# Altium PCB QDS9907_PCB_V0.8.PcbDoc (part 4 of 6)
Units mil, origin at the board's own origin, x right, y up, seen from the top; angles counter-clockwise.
Board outline 3410.03 x 4010.03 mil, 8 copper layers (Top Layer, GND1, INT1, INT2, PWR1, GND2, GND3, Bottom Layer), stack 81.668 mil thick; 250 components, 129 nets, 7010 pads, 701 vias.
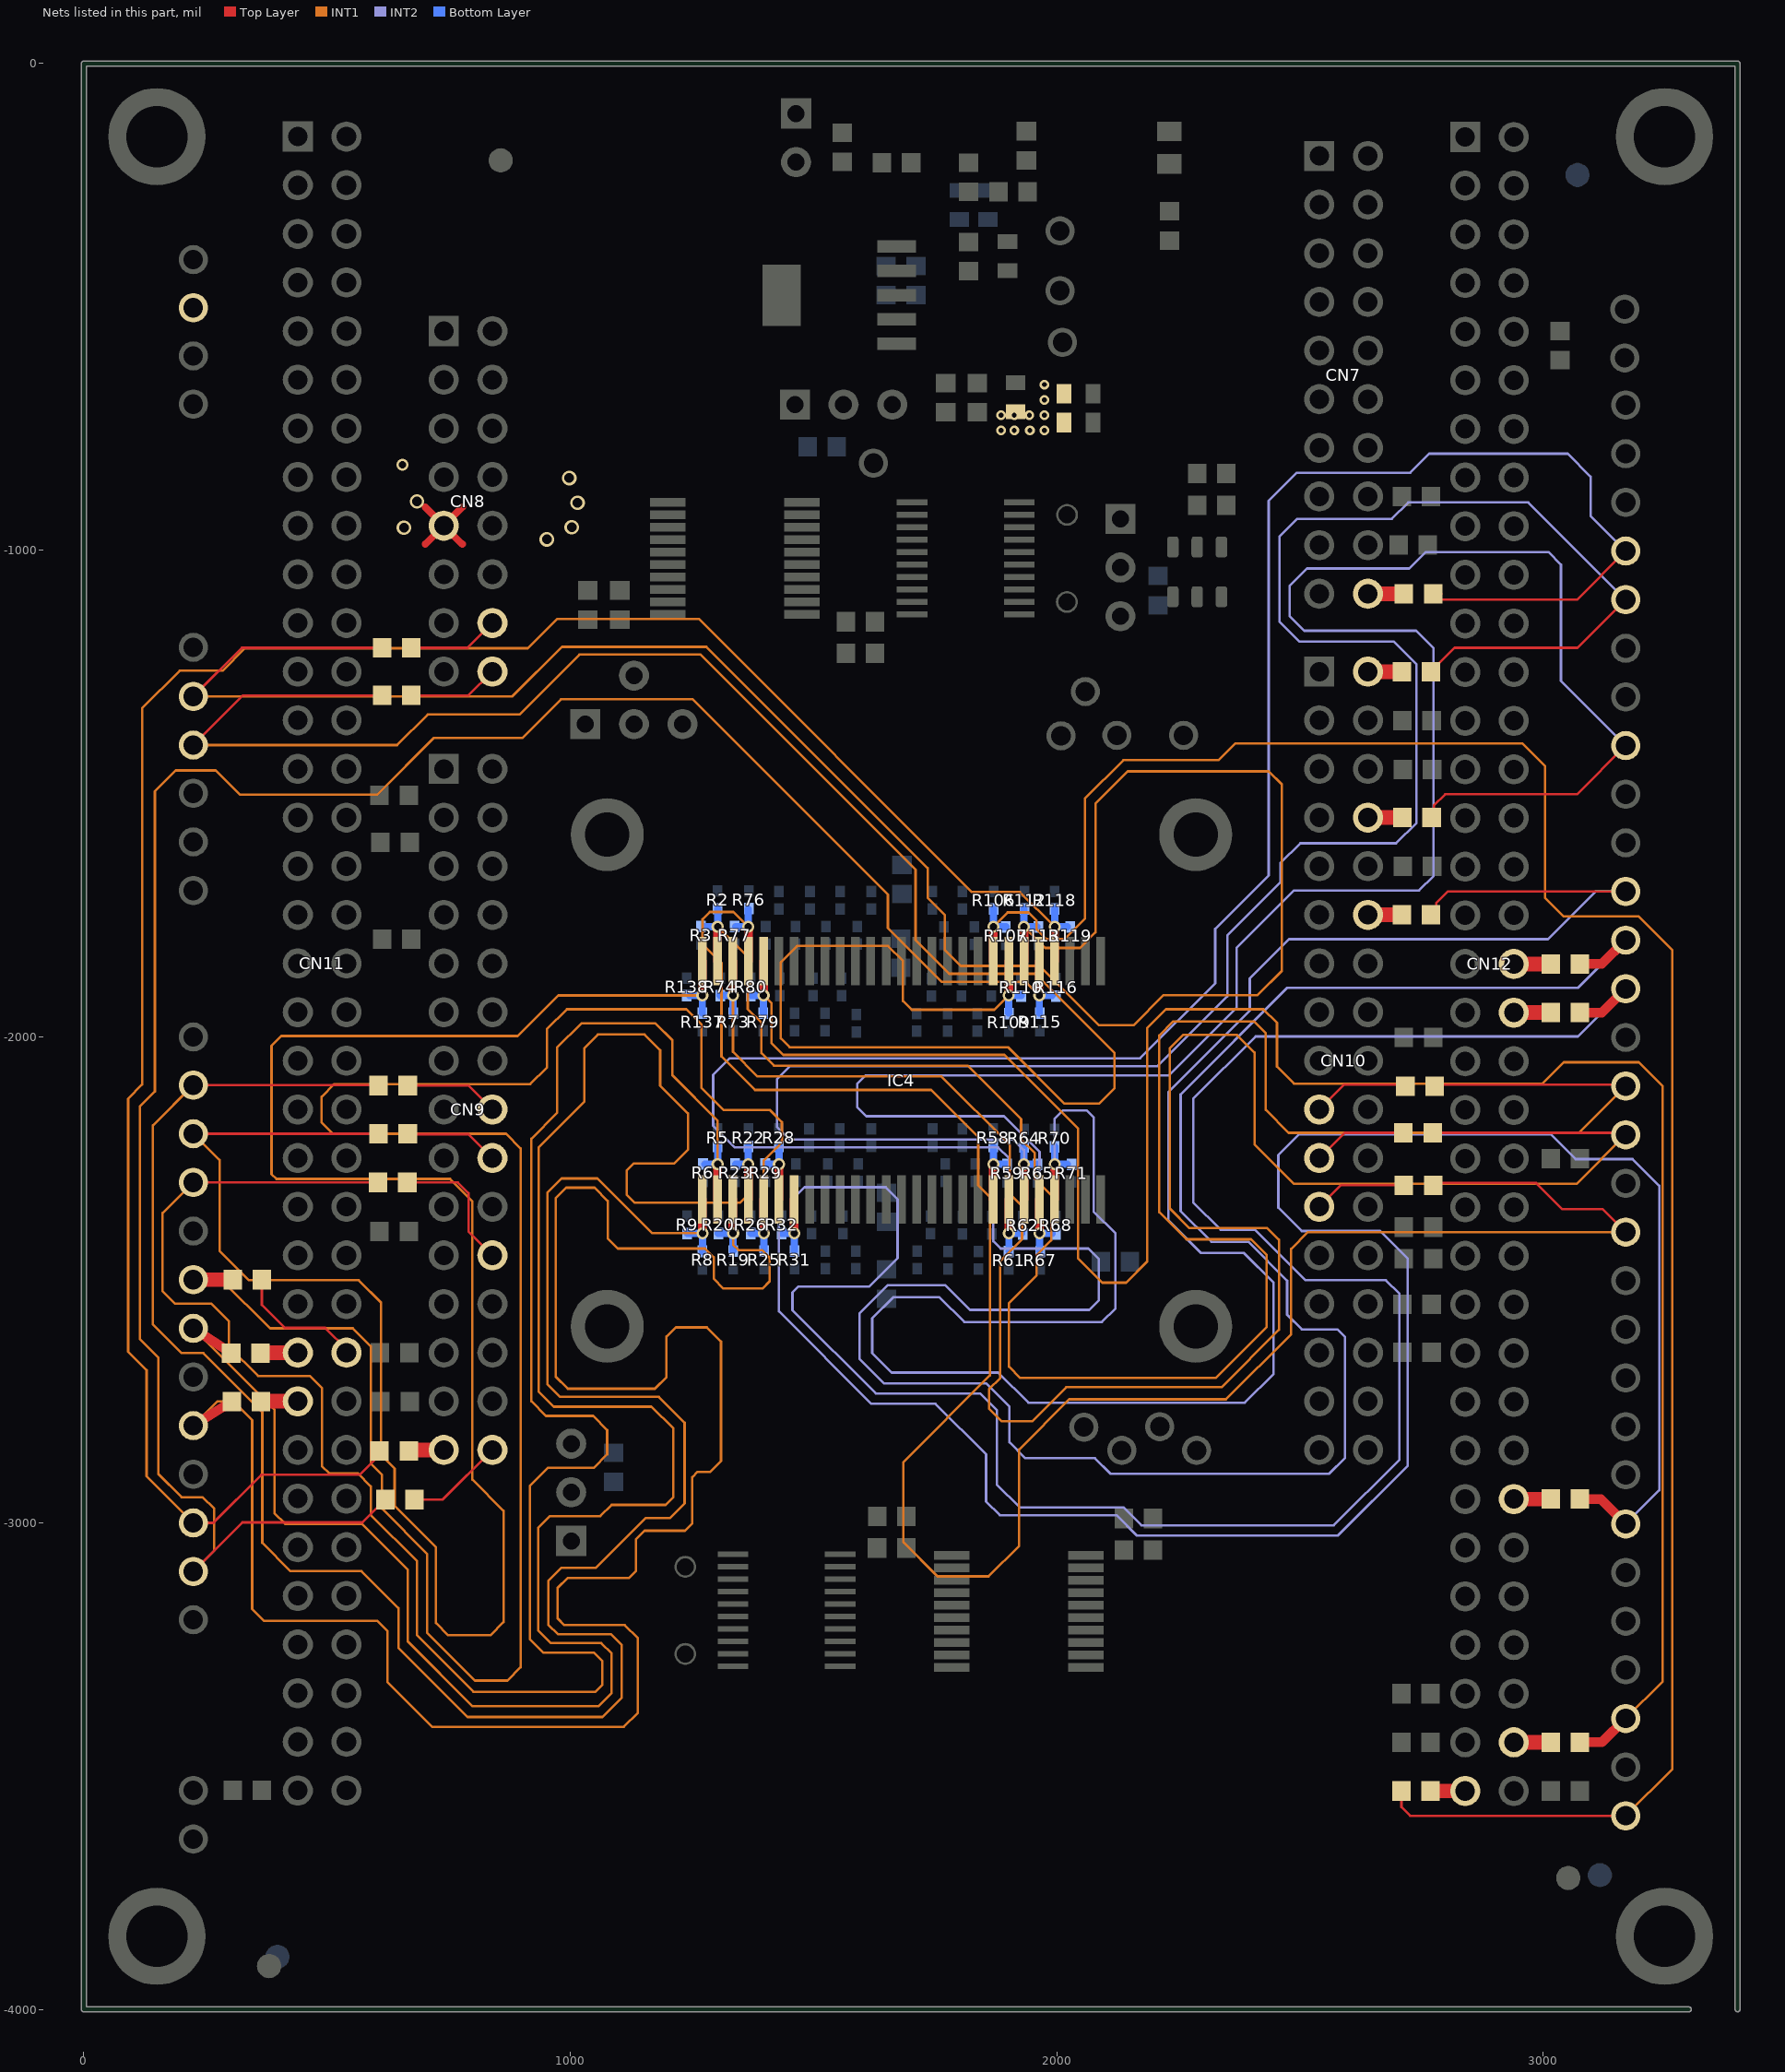
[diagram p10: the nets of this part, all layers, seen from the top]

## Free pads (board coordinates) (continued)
  round 1.28 on Bottom Overlay: ""(1652.55,-3885.99) ""(1652.55,-3885.99) ""(1652.55,-3885.73) ""(1652.55,-3884.7) ""(1652.55,-3884.39) ""(1652.55,-3884.39) ""(1652.55,-3885.99) ""(1652.55,-3885.99) ""(1652.55,-3885.73) ""(1652.55,-3884.7) ""(1652.55,-3884.39) ""(1652.55,-3884.39) ""(1652.97,-3883.68) ""(1652.97,-3883.68) ""(1652.99,-3886.76) ""(1652.99,-3886.76) ""(1653.57,-3882.65) ""(1653.57,-3882.65) ""(1653.58,-3887.79) ""(1653.58,-3887.79) ""(1653.64,-3887.9) ""(1653.64,-3887.9) ""(1653.64,-3887.9) ""(1653.64,-3887.9) ""(1654.17,-3881.62) ""(1654.17,-3881.62) ""(1654.34,-3888.82) ""(1654.34,-3888.82) ""(1654.78,-3880.59) ""(1654.78,-3880.59) ""(1655.13,-3889.84) ""(1655.13,-3889.84) ""(1655.38,-3879.57) ""(1655.38,-3879.57) ""(1655.91,-3890.87) ""(1655.91,-3890.87) ""(1655.98,-3878.54) ""(1655.98,-3878.54) ""(1656.14,-3816.83) ""(1656.14,-3816.83) ""(1656.14,-3816.83) ""(1656.14,-3816.83) ""(1656.15,-3816.88) ""(1656.15,-3816.88) ""(1656.23,-3815.85) ""(1656.23,-3815.85) ""(1656.26,-3817.91) ""(1656.26,-3817.91) ""(1656.33,-3814.82) ""(1656.33,-3814.82) ""(1656.37,-3818.94) ""(1656.37,-3818.94) ""(1656.43,-3813.8) ""(1656.43,-3813.8) ""(1656.48,-3819.96) ""(1656.48,-3819.96) ""(1656.52,-3812.77) ""(1656.52,-3812.77) ""(1656.58,-3877.51) ""(1656.58,-3877.51) ""(1656.59,-3820.99) ""(1656.59,-3820.99) ""(1656.62,-3811.74) ""(1656.62,-3811.74) ""(1656.7,-3822.02) ""(1656.7,-3891.9) ""(1656.7,-3891.9) ""(1656.71,-3810.71) ""(1656.71,-3810.71) ""(1656.81,-3809.69) ""(1656.81,-3809.69) ""(1656.81,-3823.05) ""(1656.81,-3823.05) ""(1656.9,-3808.66) ""(1656.91,-3808.66) ""(1656.92,-3824.07) ""(1656.92,-3824.07) ""(1657,-3807.63) ""(1657,-3807.63) ""(1657.03,-3825.1) ""(1657.03,-3825.1) ""(1657.1,-3806.6) ""(1657.1,-3806.6) ""(1657.1,-3825.75) ""(1657.1,-3825.75) ""(1657.1,-3825.75) ""(1657.1,-3825.75) ""(1657.19,-3876.48) ""(1657.19,-3876.48) ""(1657.19,-3805.58) ""(1657.19,-3805.58) ""(1657.2,-3826.13) ""(1657.2,-3826.13) ""(1657.29,-3876.32) ""(1657.29,-3876.32) ""(1657.29,-3876.32) ""(1657.29,-3876.32) ""(1657.29,-3804.55) ""(1657.29,-3804.55) ""(1657.38,-3876.48) ""(1657.38,-3876.48) ""(1657.38,-3803.52) ""(1657.38,-3803.52) ""(1657.43,-3803.03) ""(1657.43,-3803.03) ""(1657.43,-3803.03) ""(1657.43,-3803.03) ""(1657.45,-3827.16) ""(1657.45,-3827.16) ""(1657.49,-3892.93) ""(1657.49,-3892.93) ""(1657.57,-3802.49) ""(1657.57,-3802.49) ""(1657.71,-3828.18) ""(1657.71,-3828.18) ""(1657.72,-3893.23) ""(1657.72,-3893.23) ""(1657.72,-3893.23) ""(1657.72,-3893.23) ""(1657.83,-3801.47) ""(1657.83,-3801.47) ""(1657.95,-3877.51) ""(1657.95,-3877.51) ""(1657.97,-3829.21) ""(1658.09,-3800.44) ""(1658.09,-3800.44) ""(1658.22,-3830.24) ""(1658.22,-3830.24) ""(1658.36,-3799.41) ""(1658.36,-3799.41) ""(1658.42,-3878.35) ""(1658.42,-3878.35) ""(1658.42,-3878.35) ""(1658.42,-3878.35) ""(1658.48,-3831.27) ""(1658.48,-3831.27) ""(1658.62,-3798.38) ""(1658.62,-3798.38) ""(1658.64,-3878.54) ""(1658.64,-3878.54) ""(1658.72,-3893.95) ""(1658.73,-3893.95) ""(1658.74,-3832.29) ""(1658.74,-3832.29) ""(1658.88,-3797.35) ""(1658.89,-3797.35) ""(1659,-3833.32) ""(1659,-3833.32) ""(1659.15,-3796.33) ""(1659.15,-3796.33) ""(1659.25,-3834.35) ""(1659.25,-3834.35) ""(1659.41,-3795.3) ""(1659.41,-3795.3) ""(1659.51,-3835.38) ""(1659.51,-3835.38) ""(1659.67,-3836.02) ""(1659.67,-3836.02) ""(1659.67,-3836.02) ""(1659.67,-3836.02) ""(1659.68,-3794.27) ""(1659.68,-3794.27) ""(1659.82,-3836.41) ""(1659.82,-3836.41) ""(1659.88,-3879.57) ""(1659.88,-3879.57) ""(1659.94,-3793.24) ""(1659.94,-3793.24) ""(1660.15,-3894.98) ""(1660.15,-3894.98) ""(1660.2,-3792.22) ""(1660.2,-3792.22) ""(1660.21,-3837.43) ""(1660.21,-3837.43) ""(1660.47,-3791.19) ""(1660.47,-3791.19) ""(1660.61,-3838.46) ""(1660.61,-3838.46) ""(1660.65,-3790.48) ""(1660.65,-3790.48) ""(1660.65,-3790.48) ""(1660.65,-3790.48) ""(1660.65,-3880.22) ""(1660.65,-3880.22) ""(1660.66,-3880.22) ""(1660.66,-3880.22) ""(1660.77,-3790.16) ""(1660.77,-3790.16) ""(1661.01,-3839.49) ""(1661.01,-3839.49) ""(1661.17,-3789.13) ""(1661.17,-3789.13) ""(1661.34,-3880.59) ""(1661.34,-3880.59) ""(1661.4,-3840.52) ""(1661.4,-3840.52) ""(1661.57,-3788.11) ""(1661.57,-3788.11) ""(1661.57,-3896.01) ""(1661.57,-3896.01) ""(1661.8,-3841.54) ""(1661.8,-3841.54) ""(1661.97,-3787.08) ""(1661.97,-3787.08) ""(1662.19,-3842.57) ""(1662.19,-3842.57) ""(1662.37,-3786.05) ""(1662.37,-3786.05) ""(1662.59,-3843.6) ""(1662.59,-3843.6) ""(1662.76,-3785.02) ""(1662.76,-3785.02) ""(1662.89,-3844.39) ""(1662.89,-3844.39) ""(1662.89,-3844.39) ""(1662.89,-3844.39) ""(1663,-3897.04) ""(1663,-3897.04) ""(1663,-3844.63) ""(1663,-3844.63) ""(1663.16,-3783.99) ""(1663.16,-3783.99) ""(1663.19,-3881.62) ""(1663.19,-3881.62) ""(1663.36,-3897.3) ""(1663.36,-3897.3) ""(1663.36,-3897.3) ""(1663.36,-3897.3) ""(1663.48,-3845.65) ""(1663.48,-3845.65) ""(1663.56,-3782.97) ""(1663.56,-3782.97) ""(1663.95,-3846.68) ""(1663.95,-3846.68) ""(1663.96,-3781.94) ""(1663.96,-3781.94) ""(1663.99,-3882.07) ""(1663.99,-3882.07) ""(1663.99,-3882.07) ""(1663.99,-3882.07) ""(1664.36,-3780.91) ""(1664.36,-3780.91) ""(1664.42,-3847.71) ""(1664.42,-3847.71) ""(1664.48,-3780.6) ""(1664.48,-3780.6) ""(1664.48,-3780.6) ""(1664.48,-3780.6) ""(1664.89,-3898.06) ""(1664.89,-3898.06) ""(1664.9,-3848.74) ""(1664.9,-3848.74) ""(1665.01,-3779.88) ""(1665.01,-3779.88) ""(1665.37,-3849.76) ""(1665.37,-3849.76) ""(1665.77,-3778.86) ""(1665.77,-3778.86) ""(1665.85,-3850.79) ""(1665.85,-3850.79) ""(1666.32,-3851.82) ""(1666.32,-3851.82) ""(1666.53,-3777.83) ""(1666.53,-3777.83) ""(1666.73,-3852.7) ""(1666.73,-3852.7) ""(1666.73,-3852.7) ""(1666.73,-3852.7) ""(1666.85,-3852.85) ""(1666.85,-3852.85) ""(1666.95,-3899.09) ""(1666.95,-3899.09) ""(1667.29,-3776.8) ""(1667.29,-3776.8) ""(1667.32,-3882.07) ""(1667.32,-3882.07) ""(1667.32,-3882.07) ""(1667.32,-3882.07) ""(1667.67,-3853.88) ""(1667.67,-3853.88) ""(1668.05,-3775.77) ""(1668.05,-3775.77) ""(1668.5,-3854.9) ""(1668.5,-3854.9) ""(1668.82,-3774.75) ""(1668.82,-3774.75) ""(1669.01,-3900.12) ""(1669.01,-3900.12) ""(1669.32,-3855.93) ""(1669.32,-3855.93) ""(1669.58,-3773.72) ""(1669.58,-3773.72) ""(1670.14,-3856.96) ""(1670.14,-3856.96) ""(1670.31,-3900.77) ""(1670.31,-3900.77) ""(1670.31,-3900.77) ""(1670.31,-3900.77) ""(1670.34,-3772.69) ""(1670.34,-3772.69) ""(1670.85,-3772) ""(1670.85,-3772) ""(1670.85,-3772) ""(1670.85,-3772) ""(1670.96,-3857.99) ""(1670.96,-3857.99) ""(1671.16,-3881.72) ""(1671.16,-3881.72) ""(1671.16,-3881.72) ""(1671.16,-3881.72) ""(1671.19,-3771.66) ""(1671.19,-3771.66) ""(1671.39,-3881.62) ""(1671.39,-3881.62) ""(1671.79,-3859.01) ""(1671.79,-3859.01) ""(1671.91,-3901.15) ""(1671.91,-3901.15) ""(1672.22,-3770.64) ""(1672.22,-3770.64) ""(1672.61,-3860.04) ""(1672.61,-3860.04) ""(1673.06,-3860.61) ""(1673.06,-3860.61) ""(1673.07,-3860.61) ""(1673.07,-3860.61) ""(1673.25,-3769.61) ""(1673.25,-3769.61) ""(1673.66,-3861.07) ""(1673.66,-3861.07) ""(1673.86,-3880.59) ""(1673.86,-3880.59) ""(1674.28,-3768.58) ""(1674.28,-3768.58) ""(1675,-3862.1) ""(1675,-3862.1) ""(1675.31,-3767.55) ""(1675.31,-3767.55) ""(1675.35,-3879.97) ""(1675.35,-3879.97) ""(1675.35,-3879.97) ""(1675.35,-3879.97) ""(1675.63,-3902.02) ""(1675.63,-3902.02) ""(1675.63,-3902.02) ""(1675.63,-3902.02) ""(1676.03,-3879.57) ""(1676.03,-3879.57) ""(1676.33,-3766.52) ""(1676.33,-3766.52) ""(1676.34,-3863.12) ""(1676.34,-3863.12) ""(1677.36,-3765.5) ""(1677.36,-3765.5) ""(1677.4,-3902.18) ""(1677.4,-3902.18) ""(1677.67,-3864.15) ""(1677.67,-3864.15) ""(1677.75,-3878.54) ""(1677.75,-3878.54) ""(1677.86,-3765) ""(1677.86,-3765) ""(1677.86,-3765) ""(1677.86,-3765) ""(1678.52,-3878.07) ""(1678.52,-3878.07) ""(1678.52,-3878.07) ""(1678.52,-3878.07) ""(1678.73,-3764.47) ""(1678.73,-3764.47) ""(1679.01,-3865.18) ""(1679.01,-3865.18) ""(1680.35,-3866.21) ""(1680.35,-3866.21) ""(1680.42,-3763.44) ""(1680.42,-3763.44) ""(1680.96,-3877.51) ""(1680.96,-3877.51) ""(1681.33,-3866.97) ""(1681.33,-3866.97) ""(1681.33,-3866.97) ""(1681.33,-3866.97) ""(1681.87,-3867.23) ""(1681.87,-3867.23) ""(1682.11,-3762.41) ""(1682.11,-3762.41) ""(1682.52,-3877.15) ""(1682.52,-3877.15) ""(1682.52,-3877.15) ""(1682.52,-3877.15) ""(1682.87,-3902.65) ""(1682.87,-3902.65) ""(1682.87,-3902.65) ""(1682.87,-3902.65) ""(1683.8,-3761.39) ""(1683.8,-3761.39) ""(1683.93,-3868.26) ""(1683.93,-3868.26) ""(1685.17,-3760.55) ""(1685.17,-3760.55) ""(1685.17,-3760.55) ""(1685.17,-3760.55) ""(1685.34,-3902.18) ""(1685.34,-3902.18) ""(1685.6,-3760.36) ""(1685.6,-3760.36) ""(1685.99,-3869.29) ""(1685.99,-3869.29) ""(1687.2,-3876.48) ""(1687.2,-3876.48) ""(1687.82,-3759.33) ""(1687.82,-3759.33) ""(1688.05,-3870.32) ""(1688.05,-3870.32) ""(1689.31,-3876.18) ""(1689.31,-3876.18) ""(1689.31,-3876.18) ""(1689.31,-3876.18) ""(1689.57,-3871.08) ""(1689.57,-3871.08) ""(1689.57,-3871.08) ""(1689.57,-3871.08) ""(1690.05,-3758.3) ""(1690.05,-3758.3) ""(1690.69,-3901.15) ""(1690.69,-3901.15) ""(1690.8,-3871.35) ""(1690.8,-3871.35) ""(1691.09,-3901.07) ""(1691.09,-3901.07) ""(1691.09,-3901.07) ""(1691.09,-3901.07) ""(1692.28,-3757.28) ""(1692.28,-3757.28) ""(1693.46,-3756.73) ""(1693.46,-3756.73) ""(1693.46,-3756.73) ""(1693.46,-3756.73) ""(1693.83,-3900.12) ""(1693.83,-3900.12) ""(1694.88,-3875.46) ""(1694.88,-3875.46) ""(1695.53,-3872.37) ""(1695.53,-3872.37) ""(1695.8,-3756.25) ""(1695.8,-3756.25) ""(1696.65,-3823.05) ""(1696.65,-3823.05) ""(1696.65,-3822.02) ""(1696.65,-3822.02) ""(1696.65,-3820.99) ""(1696.65,-3820.99) ""(1696.65,-3819.96) ""(1696.65,-3819.96) ""(1696.65,-3818.94) ""(1696.65,-3818.94) ""(1696.65,-3817.91) ""(1696.65,-3817.91) ""(1696.65,-3816.88) ""(1696.65,-3816.88) ""(1696.65,-3815.85) ""(1696.65,-3815.85) ""(1696.65,-3814.82) ""(1696.65,-3814.82) ""(1696.65,-3813.8) ""(1696.65,-3813.8) ""(1696.65,-3812.77) ""(1696.65,-3812.77) ""(1696.65,-3811.74) ""(1696.65,-3811.74) ""(1696.65,-3810.71) ""(1696.65,-3810.71) ""(1696.65,-3809.69) ""(1696.65,-3809.69) ""(1696.65,-3808.66) ""(1696.65,-3808.66) ""(1696.65,-3807.63) ""(1696.65,-3807.63) ""(1696.65,-3806.6) ""(1696.65,-3806.6) ""(1696.69,-3824.07) ""(1696.69,-3824.07) ""(1696.71,-3805.58) ""(1696.71,-3805.58) ""(1696.74,-3825.1) ""(1696.74,-3825.1) ""(1696.76,-3804.55) ""(1696.76,-3804.55) ""(1696.78,-3899.09) ""(1696.78,-3899.09) ""(1696.8,-3826.13) ""(1696.8,-3826.13) ""(1696.82,-3803.52) ""(1696.82,-3803.52) ""(1696.86,-3827.16) ""(1696.86,-3827.16) ""(1696.87,-3802.49) ""(1696.87,-3802.49) ""(1696.92,-3828.18) ""(1696.92,-3828.18) ""(1696.93,-3801.47) ""(1696.93,-3801.47) ""(1696.97,-3829.21) ""(1696.98,-3800.44) ""(1696.98,-3800.44) ""(1697.03,-3830.24) ""(1697.03,-3830.24) ""(1697.03,-3799.41) ""(1697.03,-3799.41) ""(1697.09,-3831.27) ""(1697.09,-3798.38) ""(1697.09,-3831.27) ""(1697.09,-3798.38) ""(1697.14,-3797.35) ""(1697.14,-3797.35) ""(1697.15,-3832.29) ""(1697.15,-3832.29) ""(1697.2,-3796.33) ""(1697.2,-3796.33) ""(1697.2,-3833.32) ""(1697.2,-3833.32) ""(1697.25,-3795.3) ""(1697.25,-3795.3) ""(1697.26,-3834.35) ""(1697.26,-3834.35) ""(1697.3,-3794.27) ""(1697.3,-3794.27) ""(1697.32,-3835.38) ""(1697.32,-3835.38) ""(1697.36,-3793.24) ""(1697.36,-3793.24) ""(1697.37,-3836.41) ""(1697.37,-3836.41) ""(1697.41,-3792.22) ""(1697.41,-3792.22) ""(1697.43,-3837.43) ""(1697.43,-3837.43) ""(1697.47,-3791.19) ""(1697.47,-3791.19) ""(1697.49,-3838.46) ""(1697.49,-3838.46) ""(1697.52,-3790.16) ""(1697.52,-3790.16) ""(1697.55,-3839.49) ""(1697.55,-3839.49) ""(1697.58,-3789.13) ""(1697.58,-3789.13) ""(1697.6,-3840.52) ""(1697.6,-3840.52) ""(1697.63,-3788.11) ""(1697.63,-3788.11) ""(1697.75,-3841.54) ""(1697.75,-3841.54) ""(1697.9,-3787.08) ""(1697.9,-3787.08) ""(1697.97,-3842.57) ""(1697.97,-3842.57) ""(1698.16,-3786.05) ""(1698.16,-3786.05) ""(1698.19,-3843.6) ""(1698.19,-3843.6) ""(1698.34,-3898.55) ""(1698.34,-3898.55) ""(1698.34,-3898.55) ""(1698.34,-3898.55) ""(1698.41,-3844.63) ""(1698.41,-3844.63) ""(1698.43,-3785.02) ""(1698.43,-3785.02) ""(1698.63,-3845.65) ""(1698.63,-3845.65) ""(1698.69,-3783.99) ""(1698.69,-3783.99) ""(1698.85,-3846.68) ""(1698.85,-3846.68) ""(1698.95,-3782.97) ""(1698.95,-3782.97) ""(1699.04,-3898.06) ""(1699.04,-3898.06) ""(1699.07,-3847.71) ""(1699.07,-3847.71) ""(1699.22,-3781.94) ""(1699.22,-3781.94) ""(1699.29,-3848.74) ""(1699.29,-3848.74) ""(1699.48,-3780.91) ""(1699.48,-3780.91) ""(1699.51,-3849.76) ""(1699.51,-3849.76) ""(1699.74,-3779.88) ""(1699.74,-3779.88) ""(1699.8,-3850.79) ""(1699.8,-3850.79) ""(1700.01,-3778.86) ""(1700.01,-3778.86) ""(1700.13,-3851.82) ""(1700.13,-3851.82) ""(1700.26,-3873.4) ""(1700.26,-3873.4) ""(1700.27,-3777.83) ""(1700.27,-3777.83) ""(1700.45,-3852.85) ""(1700.45,-3852.85) ""(1700.51,-3897.04) ""(1700.51,-3897.04) ""(1700.54,-3776.8) ""(1700.54,-3776.8) ""(1700.77,-3755.22) ""(1700.77,-3755.22) ""(1700.78,-3853.88) ""(1700.78,-3853.88) ""(1700.8,-3775.77) ""(1700.8,-3775.77) ""(1701.1,-3854.9) ""(1701.1,-3854.9) ""(1701.31,-3774.75) ""(1701.31,-3774.75) ""(1701.43,-3855.93) ""(1701.43,-3855.93) ""(1701.95,-3773.72) ""(1701.95,-3773.72) ""(1701.98,-3856.96) ""(1701.98,-3856.96) ""(1701.98,-3896.01) ""(1701.98,-3896.01) ""(1702.59,-3772.69) ""(1702.59,-3772.69) ""(1702.66,-3857.99) ""(1702.66,-3857.99) ""(1702.7,-3754.82) ""(1702.7,-3754.82) ""(1702.7,-3754.82) ""(1702.7,-3754.82) ""(1702.77,-3874.43) ""(1702.77,-3874.43) ""(1703.23,-3771.66) ""(1703.23,-3771.66) ""(1703.35,-3859.01) ""(1703.35,-3859.01) ""(1703.45,-3894.98) ""(1703.45,-3894.98) ""(1703.88,-3770.64) ""(1703.88,-3770.64) ""(1704.16,-3874.25) ""(1704.16,-3874.25) ""(1704.16,-3874.25) ""(1704.16,-3874.25) ""(1704.4,-3860.04) ""(1704.4,-3860.04) ""(1704.92,-3893.95) ""(1704.92,-3893.95) ""(1705.24,-3769.61) ""(1705.24,-3769.61) ""(1705.55,-3861.07) ""(1705.55,-3861.07) ""(1706.38,-3892.93) ""(1706.38,-3892.93) ""(1707.17,-3768.58) ""(1707.17,-3768.58) ""(1707.39,-3862.1) ""(1707.39,-3862.1) ""(1707.85,-3891.9) ""(1707.85,-3891.9) ""(1707.91,-3891.86) ""(1707.91,-3891.86) ""(1707.91,-3891.86) ""(1707.91,-3891.86) ""(1708.94,-3890.87) ""(1708.94,-3890.87) ""(1710.02,-3889.84) ""(1710.02,-3889.84) ""(1711.09,-3888.82) ""(1711.09,-3888.82) ""(1711.83,-3754.19) ""(1711.83,-3754.19) ""(1712.02,-3754.18) ""(1712.02,-3754.18) ""(1712.02,-3754.18) ""(1712.02,-3754.18) ""(1712.16,-3887.79) ""(1712.16,-3887.79) ""(1712.37,-3754.19) ""(1712.37,-3754.19) ""(1713.24,-3886.76) ""(1713.24,-3886.76) ""(1713.51,-3863.12) ""(1713.51,-3863.12) ""(1714.07,-3863.12) ""(1714.07,-3863.12) ""(1714.31,-3885.73) ""(1714.31,-3885.73) ""(1715.38,-3884.7) ""(1715.38,-3884.7) ""(1715.66,-3884.44) ""(1715.66,-3884.44) ""(1715.66,-3884.44) ""(1715.66,-3884.44) ""(1716.29,-3768.58) ""(1716.29,-3768.58) ""(1716.38,-3883.68) ""(1716.39,-3883.68) ""(1716.89,-3862.1) ""(1716.89,-3862.1) ""(1717.36,-3882.65) ""(1717.36,-3882.65) ""(1718.25,-3769.61) ""(1718.25,-3769.61) ""(1718.34,-3861.07) ""(1718.34,-3861.07) ""(1718.34,-3881.62) ""(1718.34,-3881.62) ""(1719,-3770.64) ""(1719,-3770.64) ""(1719.32,-3880.59) ""(1719.32,-3880.59) ""(1719.37,-3860.04) ""(1719.37,-3860.04) ""(1719.75,-3771.66) ""(1719.75,-3771.66) ""(1720.29,-3879.57) ""(1720.29,-3879.57) ""(1720.4,-3859.01) ""(1720.4,-3859.01) ""(1720.5,-3772.69) ""(1720.5,-3772.69) ""(1720.62,-3754.5) ""(1720.62,-3754.5) ""(1720.62,-3754.5) ""(1720.62,-3754.5) ""(1720.85,-3857.99) ""(1720.85,-3857.99) ""(1721.07,-3773.72) ""(1721.07,-3773.72) ""(1721.25,-3856.96) ""(1721.27,-3878.54) ""(1721.27,-3878.54) ""(1721.51,-3774.75) ""(1721.51,-3774.75) ""(1721.66,-3855.93) ""(1721.66,-3855.93) ""(1721.93,-3877.84) ""(1721.93,-3877.84) ""(1721.93,-3877.84) ""(1721.93,-3877.84) ""(1721.95,-3775.77) ""(1721.95,-3775.77) ""(1722.06,-3854.9) ""(1722.06,-3854.9) ""(1722.39,-3776.8) ""(1722.39,-3776.8) ""(1722.41,-3877.51) ""(1722.41,-3877.51) ""(1722.46,-3853.88) ""(1722.46,-3853.88) ""(1722.81,-3777.83) ""(1722.81,-3777.83) ""(1722.87,-3852.85) ""(1722.87,-3852.85) ""(1723.12,-3778.86) ""(1723.12,-3778.86) ""(1723.27,-3851.82) ""(1723.27,-3851.82) ""(1723.3,-3755.22) ""(1723.3,-3755.22) ""(1723.43,-3779.88) ""(1723.43,-3779.88) ""(1723.53,-3850.79) ""(1723.53,-3850.79) ""(1723.71,-3849.76) ""(1723.71,-3849.76) ""(1723.74,-3780.91) ""(1723.74,-3780.91) ""(1723.89,-3848.74) ""(1723.89,-3848.74) ""(1723.9,-3876.48) ""(1723.9,-3876.48) ""(1723.91,-3781.94) ""(1723.91,-3781.94) ""(1724.06,-3847.71) ""(1724.06,-3847.71) ""(1724.08,-3782.97) ""(1724.08,-3782.97) ""(1724.24,-3846.68) ""(1724.24,-3846.68) ""(1724.24,-3783.99) ""(1724.24,-3783.99) ""(1724.41,-3785.02) ""(1724.41,-3785.02) ""(1724.42,-3845.65) ""(1724.42,-3845.65) ""(1724.57,-3786.05) ""(1724.57,-3786.05) ""(1724.6,-3844.63) ""(1724.6,-3844.63) ""(1724.74,-3787.08) ""(1724.74,-3787.08) ""(1724.77,-3843.6) ""(1724.77,-3843.6) ""(1724.91,-3788.11) ""(1724.91,-3788.11) ""(1724.95,-3842.57) ""(1724.95,-3842.57) ""(1725.07,-3789.13) ""(1725.07,-3789.13) ""(1725.1,-3841.54) ""(1725.1,-3841.54) ""(1725.21,-3840.52) ""(1725.21,-3840.52) ""(1725.24,-3790.16) ""(1725.24,-3790.16) ""(1725.33,-3839.49) ""(1725.33,-3839.49) ""(1725.38,-3875.46) ""(1725.38,-3875.46) ""(1725.4,-3791.19) ""(1725.4,-3791.19) ""(1725.44,-3838.46) ""(1725.44,-3838.46) ""(1725.49,-3792.22) ""(1725.49,-3792.22) ""(1725.55,-3837.43) ""(1725.55,-3837.43) ""(1725.59,-3793.24) ""(1725.59,-3793.24) ""(1725.66,-3836.41) ""(1725.66,-3836.41) ""(1725.68,-3794.27) ""(1725.68,-3794.27) ""(1725.77,-3835.38) ""(1725.77,-3835.38) ""(1725.78,-3795.3) ""(1725.78,-3795.3) ""(1725.88,-3796.33) ""(1725.88,-3796.33) ""(1725.88,-3834.35) ""(1725.88,-3834.35) ""(1725.97,-3797.35) ""(1725.97,-3797.35) ""(1726,-3833.32) ""(1726,-3833.32) ""(1726.07,-3798.38) ""(1726.07,-3798.38) ""(1726.11,-3832.29) ""(1726.11,-3832.29) ""(1726.17,-3799.41) ""(1726.17,-3799.41) ""(1726.22,-3831.27) ""(1726.22,-3831.27) ""(1726.26,-3800.44) ""(1726.26,-3800.44) ""(1726.33,-3830.24) ""(1726.33,-3830.24) ""(1726.36,-3801.47) ""(1726.36,-3801.47) ""(1726.41,-3802.49) ""(1726.41,-3802.49) ""(1726.44,-3829.21) ""(1726.44,-3829.21) ""(1726.46,-3803.52) ""(1726.46,-3803.52) ""(1726.52,-3804.55) ""(1726.52,-3804.55) ""(1726.55,-3828.18) ""(1726.55,-3828.18) ""(1726.57,-3805.58) ""(1726.57,-3805.58) ""(1726.62,-3806.6) ""(1726.62,-3806.6) ""(1726.67,-3827.16) ""(1726.67,-3827.16) ""(1726.67,-3807.63) ""(1726.67,-3807.63) ""(1726.71,-3826.13) ""(1726.71,-3826.13) ""(1726.72,-3808.66) ""(1726.72,-3808.66) ""(1726.74,-3825.1) ""(1726.74,-3825.1) ""(1726.76,-3824.07) ""(1726.76,-3824.07) ""(1726.77,-3809.69) ""(1726.77,-3809.69) ""(1726.79,-3823.05) ""(1726.79,-3823.05) ""(1726.82,-3822.02) ""(1726.82,-3822.02) ""(1726.82,-3810.71) ""(1726.82,-3810.71) ""(1726.85,-3820.99) ""(1726.85,-3820.99) ""(1726.87,-3874.43) ""(1726.87,-3874.43) ""(1726.87,-3819.96) ""(1726.87,-3819.96) ""(1726.88,-3811.74) ""(1726.88,-3811.74) ""(1726.9,-3818.94) ""(1726.9,-3818.94) ""(1726.93,-3812.77) ""(1726.93,-3812.77) ""(1726.93,-3817.91) ""(1726.93,-3817.91) ""(1726.95,-3816.88) ""(1726.95,-3816.88) ""(1726.98,-3813.8) ""(1726.98,-3813.8) ""(1726.98,-3815.85) ""(1726.98,-3815.85) ""(1727.01,-3814.82) ""(1727.01,-3814.82) ""(1727.12,-3756.25) ""(1727.12,-3756.25) ""(1728.35,-3873.4) ""(1728.35,-3873.4) ""(1728.9,-3756.72) ""(1728.9,-3756.72) ""(1728.9,-3756.72) ""(1728.9,-3756.72) ""(1729.84,-3872.37) ""(1729.84,-3872.37) ""(1730.27,-3757.28) ""(1730.27,-3757.28) ""(1730.61,-3871.84) ""(1730.61,-3871.84) ""(1730.61,-3871.84) ""(1730.61,-3871.84) ""(1731.6,-3871.35) ""(1731.6,-3871.35) ""(1732.85,-3758.3) ""(1732.85,-3758.3) ""(1733.66,-3870.32) ""(1733.66,-3870.32) ""(1735.31,-3759.29) ""(1735.31,-3759.29) ""(1735.31,-3759.29) ""(1735.31,-3759.29) ""(1735.4,-3759.33) ""(1735.4,-3759.33) ""(1735.72,-3869.29) ""(1735.72,-3869.29) ""(1737.45,-3760.36) ""(1737.45,-3760.36) ""(1737.77,-3868.26) ""(1737.77,-3868.26) ""(1738.49,-3867.91) ""(1738.49,-3867.91) ""(1738.49,-3867.91) ""(1738.49,-3867.91) ""(1739.51,-3761.39) ""(1739.51,-3761.39) ""(1739.64,-3867.23) ""(1739.64,-3867.23) ""(1741.05,-3762.15) ""(1741.05,-3762.15) ""(1741.05,-3762.15) ""(1741.05,-3762.15) ""(1741.4,-3866.21) ""(1741.4,-3866.21) ""(1741.41,-3762.41) ""(1741.41,-3762.41) ""(1742.85,-3763.44) ""(1742.85,-3763.44) ""(1743.17,-3865.18) ""(1743.17,-3865.18) ""(1744.29,-3764.47) ""(1744.29,-3764.47) ""(1744.93,-3864.15) ""(1744.93,-3864.15) ""(1745.73,-3765.5) ""(1745.73,-3765.5) ""(1746.19,-3863.41) ""(1746.19,-3863.41) ""(1746.19,-3863.41) ""(1746.19,-3863.41) ""(1746.54,-3863.12) ""(1746.54,-3863.12) ""(1747.17,-3766.52) ""(1747.17,-3766.52) ""(1747.73,-3766.93) ""(1747.73,-3766.93) ""(1747.73,-3766.93) ""(1747.73,-3766.93) ""(1747.78,-3862.1) ""(1747.78,-3862.1) ""(1748.36,-3767.55) ""(1748.36,-3767.55) ""(1749.01,-3861.07) ""(1749.01,-3861.07) ""(1749.39,-3768.58) ""(1749.39,-3768.58) ""(1750.25,-3860.04) ""(1750.25,-3860.04) ""(1750.42,-3769.61) ""(1750.42,-3769.61) ""(1751.45,-3770.64) ""(1751.45,-3770.64) ""(1751.48,-3859.01) ""(1751.48,-3859.01) ""(1751.86,-3858.7) ""(1751.86,-3858.7) ""(1751.86,-3858.7) ""(1751.86,-3858.7) ""(1752.35,-3857.99) ""(1752.35,-3857.99) ""(1752.47,-3771.66) ""(1752.47,-3771.66) ""(1753.07,-3856.96) ""(1753.07,-3856.96) ""(1753.5,-3772.69) ""(1753.5,-3772.69) ""(1753.78,-3855.93) ""(1753.79,-3855.93) ""(1753.8,-3772.99) ""(1753.8,-3772.99) ""(1753.8,-3772.99) ""(1753.8,-3772.99) ""(1754.36,-3773.72) ""(1754.36,-3773.72) ""(1754.5,-3854.9) ""(1754.5,-3854.9) ""(1755.15,-3774.75) ""(1755.15,-3774.75) ""(1755.22,-3853.88) ""(1755.22,-3853.88) ""(1755.93,-3852.85) ""(1755.93,-3852.85) ""(1755.93,-3775.77) ""(1755.93,-3775.77) ""(1756.65,-3851.82) ""(1756.65,-3851.82) ""(1756.72,-3776.8) ""(1756.72,-3776.8) ""(1756.96,-3851.37) ""(1756.96,-3851.37) ""(1756.96,-3851.37) ""(1756.96,-3851.37) ""(1757.31,-3850.79) ""(1757.31,-3850.79) ""(1757.51,-3777.83) ""(1757.51,-3777.83) ""(1757.92,-3778.37) ""(1757.92,-3778.37) ""(1757.92,-3778.37) ""(1757.92,-3778.37) ""(1757.92,-3849.76) ""(1757.92,-3849.76) ""(1758.16,-3778.86) ""(1758.16,-3778.86) ""(1758.54,-3848.74) ""(1758.54,-3848.74) ""(1758.68,-3779.88) ""(1758.68,-3779.88) ""(1759.16,-3847.71) ""(1759.16,-3847.71) ""(1759.19,-3780.91) ""(1759.19,-3780.91) ""(1759.71,-3781.94) ""(1759.71,-3781.94) ""(1759.77,-3846.68) ""(1759.78,-3846.68) ""(1759.81,-3846.62) ""(1759.81,-3846.62) ""(1759.81,-3846.62) ""(1759.81,-3846.62) ""(1760.18,-3845.65) ""(1760.18,-3845.65) ""(1760.22,-3782.97) ""(1760.22,-3782.97) ""(1760.57,-3844.63) ""(1760.57,-3844.63) ""(1760.74,-3783.99) ""(1760.74,-3783.99) ""(1760.96,-3843.6) ""(1760.96,-3843.6) ""(1761.25,-3785.02) ""(1761.25,-3785.02) ""(1761.35,-3842.57) ""(1761.35,-3842.57) ""(1761.41,-3785.34) ""(1761.41,-3785.34) ""(1761.41,-3785.34) ""(1761.41,-3785.34) ""(1761.62,-3786.05) ""(1761.62,-3786.05) ""(1761.74,-3841.54) ""(1761.74,-3841.54) ""(1761.93,-3787.08) ""(1761.93,-3787.08) ""(1762.13,-3840.52) ""(1762.13,-3840.52) ""(1762.24,-3788.11) ""(1762.24,-3788.11) ""(1762.52,-3839.49) ""(1762.52,-3839.49) ""(1762.55,-3789.13) ""(1762.55,-3789.13) ""(1762.86,-3790.16) ""(1762.86,-3790.16) ""(1762.91,-3838.46) ""(1762.91,-3838.46) ""(1763.16,-3791.19) ""(1763.16,-3791.19) ""(1763.3,-3837.43) ""(1763.3,-3837.43) ""(1763.33,-3837.36) ""(1763.33,-3837.36) ""(1763.33,-3837.36) ""(1763.33,-3837.36) ""(1763.47,-3792.22) ""(1763.47,-3792.22) ""(1763.52,-3836.41) ""(1763.52,-3836.41) ""(1763.72,-3835.38) ""(1763.73,-3835.38) ""(1763.78,-3793.24) ""(1763.78,-3793.24) ""(1763.93,-3834.35) ""(1763.93,-3834.35) ""(1764.09,-3794.27) ""(1764.09,-3794.27) ""(1764.14,-3833.32) ""(1764.14,-3833.32) ""(1764.31,-3794.99) ""(1764.31,-3794.99) ""(1764.31,-3794.99) ""(1764.31,-3794.99) ""(1764.34,-3832.29) ""(1764.34,-3832.29) ""(1764.38,-3795.3) ""(1764.38,-3795.3) ""(1764.55,-3831.27) ""(1764.55,-3831.27) ""(1764.64,-3796.33) ""(1764.64,-3796.33) ""(1764.75,-3830.24) ""(1764.75,-3830.24) ""(1764.9,-3797.35) ""(1764.9,-3797.35) ""(1764.93,-3829.34) ""(1764.93,-3829.34) ""(1764.93,-3829.34) ""(1764.93,-3829.34) ""(1764.95,-3829.21) ""(1764.95,-3829.21) ""(1765.11,-3828.18) ""(1765.11,-3828.18) ""(1765.15,-3798.38) ""(1765.16,-3798.38) ""(1765.26,-3827.16) ""(1765.26,-3827.16) ""(1765.41,-3826.13) ""(1765.41,-3826.13) ""(1765.41,-3799.41) ""(1765.41,-3799.41) ""(1765.56,-3825.1) ""(1765.56,-3825.1) ""(1765.58,-3800.1) ""(1765.58,-3800.1) ""(1765.58,-3800.1) ""(1765.58,-3800.1) ""(1765.62,-3800.44) ""(1765.62,-3800.44) ""(1765.71,-3824.07) ""(1765.71,-3824.07) ""(1765.73,-3801.47) ""(1765.73,-3801.47) ""(1765.83,-3802.49) ""(1765.83,-3802.49) ""(1765.87,-3823.05) ""(1765.87,-3823.05) ""(1765.94,-3803.52) ""(1765.94,-3803.52) ""(1766.02,-3822.02) ""(1766.02,-3822.02) ""(1766.04,-3804.55) ""(1766.04,-3804.55) ""(1766.15,-3805.58) ""(1766.15,-3805.58) ""(1766.17,-3820.99) ""(1766.17,-3820.99) ""(1766.22,-3820.64) ""(1766.22,-3820.64) ""(1766.22,-3820.64) ""(1766.22,-3820.64) ""(1766.24,-3819.96) ""(1766.24,-3819.96) ""(1766.26,-3806.6) ""(1766.26,-3806.6) ""(1766.27,-3818.94) ""(1766.27,-3818.94) ""(1766.3,-3817.91) ""(1766.3,-3817.91) ""(1766.33,-3816.88) ""(1766.33,-3816.88) ""(1766.36,-3815.85) ""(1766.36,-3815.85) ""(1766.36,-3807.63) ""(1766.36,-3807.63) ""(1766.39,-3814.82) ""(1766.39,-3814.82) ""(1766.42,-3813.8) ""(1766.42,-3813.8) ""(1766.45,-3812.77) ""(1766.45,-3812.77) ""(1766.47,-3808.66) ""(1766.47,-3808.66) ""(1766.48,-3811.74) ""(1766.48,-3811.74) ""(1766.51,-3810.71) ""(1766.51,-3810.71) ""(1766.54,-3809.69) ""(1766.54,-3809.69) ""(1766.54,-3809.38) ""(1766.54,-3809.38) ""(1766.55,-3809.38) ""(1766.55,-3809.38)
  round 1.29 on Bottom Overlay: ""(1656.7,-3822.02) ""(1657.97,-3829.21) ""(1696.97,-3829.21) ""(1721.26,-3856.96)
  round 1.8 on Bottom Overlay: ""(1696.65,-3823.36) ""(1696.65,-3823.36) ""(1696.65,-3806.72) ""(1696.65,-3806.72) ""(1697.63,-3840.98) ""(1697.63,-3840.98) ""(1697.63,-3788.13) ""(1697.63,-3788.13) ""(1697.63,-3840.98) ""(1697.63,-3840.98) ""(1697.63,-3788.13) ""(1697.63,-3788.13) ""(1699.59,-3850.11) ""(1699.59,-3850.11) ""(1699.59,-3850.11) ""(1699.59,-3850.11) ""(1700.89,-3775.4) ""(1700.89,-3775.4) ""(1700.89,-3775.4) ""(1700.89,-3775.4) ""(1701.55,-3856.31) ""(1701.55,-3856.31) ""(1701.55,-3856.31) ""(1701.55,-3856.31) ""(1703.51,-3859.25) ""(1703.51,-3859.25) ""(1704.16,-3770.18) ""(1704.16,-3770.18) ""(1704.16,-3770.18) ""(1704.16,-3770.18) ""(1709.06,-3767.58) ""(1709.06,-3767.58) ""(1709.06,-3767.58) ""(1709.06,-3767.58) ""(1710.36,-3862.84) ""(1710.36,-3862.84) ""(1710.36,-3862.84) ""(1710.36,-3862.84) ""(1713.95,-3863.16) ""(1713.95,-3863.16) ""(1713.95,-3863.16) ""(1713.95,-3863.16) ""(1714.28,-3767.58) ""(1714.28,-3767.58) ""(1714.28,-3767.58) ""(1714.28,-3767.58) ""(1717.55,-3861.86) ""(1717.55,-3861.86) ""(1718.2,-3769.53) ""(1718.2,-3769.53) ""(1718.2,-3769.53) ""(1718.2,-3769.53) ""(1720.81,-3773.12) ""(1720.81,-3773.12) ""(1722.77,-3777.69) ""(1722.77,-3777.69) ""(1722.77,-3777.69) ""(1722.77,-3777.69) ""(1723.42,-3851.42) ""(1723.42,-3851.42) ""(1723.42,-3851.42) ""(1723.42,-3851.42) ""(1726.69,-3826.95) ""(1726.69,-3826.95) ""(1727.02,-3814.55) ""(1727.02,-3814.55) ""(1727.02,-3814.55) ""(1727.02,-3814.55)

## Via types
v1: diameter 25, hole 15, Top Layer to Bottom Layer, tented both sides, 623 vias
v2: diameter 20, hole 10, Top Layer to Bottom Layer, tented both sides, 59 vias
v3: diameter 30, hole 20, Top Layer to Bottom Layer, tented both sides, 19 vias

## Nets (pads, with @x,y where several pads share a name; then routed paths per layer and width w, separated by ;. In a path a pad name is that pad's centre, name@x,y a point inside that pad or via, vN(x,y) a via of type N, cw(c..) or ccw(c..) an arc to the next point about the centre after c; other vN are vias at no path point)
+5V0: +5V0.1 C19.1 C20.1 CN8.9 L1.1 | length 215
  Top Layer w15: 702,-988 CN8.9@740,-950 ; 702,-912 CN8.9@740,-950 ; 778,-988 CN8.9@740,-950 ; 778,-912 CN8.9@740,-950
  other v1: 655,-825
  other v2: 1886,-754 1913,-754 1945,-754 1975,-754 1886,-722.67 1913,-722.67 1944,-722.67 1975,-722.67 1975,-691.33 1975,-660
  other v3: 952,-978 658,-954 1003,-953 1015,-903 685,-900 998,-852
A0: A0.1 IC4.3 R18.2 R19.2 R20.2 | length 4527.1
  Top Layer w5: R18.2@304,-2756 R18.2@304,-2751
  Top Layer w18: v1@1334.54,-2404.54 IC4.3@1334.54,-2335
  Top Layer w20: A0.1@225,-2800 R18.2@304,-2751
  INT1 w5: A0.1@225,-2800 275,-2750 307,-2750 346,-2789 346,-3177 370,-3201 603,-3201 624,-3222 624,-3327 716,-3419 1110,-3419 1139,-3390 1139,-3237 1112,-3210 988,-3210 974,-3196 974,-3134 995,-3113 1121,-3113 1135,-3099 1135,-3034 1153,-3016 1236,-3016 1251,-3001 1251,-2906 1262,-2895 1288,-2895 1310,-2873 1310,-2627 1281,-2598 1217,-2598 1198,-2617 1198,-2700 1174,-2724 995,-2724 970,-2699 970,-2333 992,-2311 1050,-2311 1077,-2338 1077,-2415 1098,-2436 1277,-2436 1295,-2454 1295,-2498 1315,-2518 1395,-2518 1410,-2503 1410,-2455 1394,-2439 1346,-2439 1334.99,-2427.99 v1(1334.99,-2404.54)
  Bottom Layer w5: v1@1334.54,-2405 v1(1334.99,-2404.54) ; R19.2@1334.99,-2440.54 R19.2@1335.45,-2441
  Bottom Layer w15: R20.2@1304.45,-2405 v1@1334.54,-2405 ; R19.2@1334.99,-2440.54 v1(1334.99,-2404.54)
A0_1: CN11.53 R18.1 | length 68
  Top Layer w30: R18.1@373,-2750 CN11.53@440,-2750 CN11.53@441,-2750
A1: A1.1 IC4.4 R21.1 R22.2 R23.2 | length 4527.9
  Top Layer w5: R21.1@303,-2651 R21.1@303,-2646
  Top Layer w18: IC4.4@1366.04,-2335 v1(1366.04,-2262.46)
  Top Layer w20: A1.1@225,-2600 R21.1@303,-2651
  INT1 w5: A1.1@225,-2600 392,-2767 392,-2980 414,-3002 571.5,-3002 666,-3096.5 666,-3244 799,-3377 1058,-3377 1085,-3350 1085,-3268 1064,-3247 960,-3247 934,-3221 934,-3010 958,-2986 1062,-2986 1085,-2963 1196,-2963 1212,-2947 1212,-2806 1167,-2761 966,-2761 935,-2730 935,-2228 1029,-2134 1029,-2024 1057,-1996 1153,-1996 1185,-2028 1185,-2101 1242,-2158 1242,-2233 1214,-2261 1131,-2261 1116,-2276 1116,-2325 1133,-2342 1349,-2342 1366.04,-2324.96 v1(1366.04,-2262.46)
  Bottom Layer w15: R23.2@1339.96,-2262.46 v1(1366.04,-2262.46) R22.2@1366.04,-2226.46
A1_1: CN11.51 R21.2 | length 68
  Top Layer w30: R21.2@372,-2650 CN11.51@440,-2650
A2: A2.1 IC4.5 R24.1 R25.2 R26.2 | length 4549.7
  Top Layer w18: v1@1397.54,-2404.54 IC4.5@1397.54,-2335
  Top Layer w30: A2.1@225,-2500 R24.1@306,-2500
  INT1 w5: A2.1@225,-2500 283,-2500 383,-2600 553,-2600 590,-2637 590,-2878 613,-2901 613,-2971 706,-3064 706,-3226 804,-3324 871,-3324 898,-3297 898,-2230 868,-2200 512,-2200 489,-2177 489,-2124 515,-2098 918,-2098 952,-2064 952,-1985 993,-1944 1239,-1944 1270,-1975 1270,-2106 1315,-2151 1410,-2151 1435,-2176 1435,-2218 1397.98,-2255.02 v1(1397.98,-2404.54)
  Bottom Layer w15: R26.2@1371.91,-2404.54 v1(1397.98,-2404.54) R25.2@1397.98,-2440.54
A2_1: CN11.52 R24.2 | length 277.8
  Top Layer w5: R24.2@366,-2500 366,-2552 413,-2599 496.24,-2599 CN11.52@542.12,-2644.88
  Top Layer w20: CN11.52@540,-2650 cw(c547.24,-2650) 542.11,-2644.89 CN11.52@540,-2650
A3: A3.1 IC4.6 R27.1 R28.2 R29.2 | length 4563.5
  Top Layer w18: IC4.6@1429.03,-2335 v1(1429.03,-2262.46)
  Top Layer w20: R27.1@3076,-2951 3119,-2951 A3.1@3170,-3002
  INT2 w5: v1(1429.03,-2262.46) 1429.03,-2565.03 1619,-2755 1751,-2755 1855,-2859 1855,-2956 1883,-2984 2123,-2984 2165,-3026 2578,-3026 2722,-2882 2722,-2457 2665,-2400 2504,-2400 2456,-2352 2456,-2244 2499,-2201 3016,-2201 3067,-2252 3184,-2252 3239,-2307 3239,-2933 A3.1@3170,-3002
  Bottom Layer w15: R29.2@1402.95,-2262.46 v1(1429.03,-2262.46) R28.2@1429.03,-2226.46
A3_1: CN12.58 R27.2 | length 76
  Top Layer w30: CN12.58@2940,-2951 R27.2@3016,-2951
A4: A4.1 IC4.7 R30.1 R31.2 R32.2 | length 4569
  Top Layer w18: v1@1460.53,-2404.54 IC4.7@1460.53,-2335
  Top Layer w20: R30.1@3076,-1951 3121,-1951 A4.1@3170,-1902
  INT2 w5: v1(1460.98,-2404.54) 1460.98,-2331.02 1482,-2310 1648.55,-2310 1673,-2334.45 1673,-2456 1615,-2514 1469,-2514 1457,-2526 1457,-2563 1628,-2734 1843,-2734 1877,-2768 1877,-2921 1924,-2968 2137,-2968 2174,-3005 2570,-3005 2705,-2870 2705,-2529 2677,-2501 2512,-2501 2408,-2397 2337,-2397 2281,-2341 2281,-2128 2409,-2000 3072,-2000 A4.1@3170,-1902
  Bottom Layer w15: R32.2@1434.9,-2404.54 v1(1460.98,-2404.54) R31.2@1460.98,-2440.54
A4_1: CN12.38 R30.2 | length 76
  Top Layer w30: CN12.38@2940,-1951 R30.2@3016,-1951
A5: A5.1 IC4.20 R57.1 R58.2 R59.2 | length 4536
  Top Layer w18: IC4.20@1869.98,-2335 v1(1869.98,-2262.46)
  Top Layer w20: R57.1@3076,-1851 3121,-1851 A5.1@3170,-1802
  INT2 w5: v1(1869.98,-2262.46) 1869.98,-2421 1884.98,-2436 2065,-2436 2087,-2458 2087,-2542 2067,-2562 1822,-2562 1771,-2511 1653,-2511 1595,-2569 1595,-2663 1645,-2713 1855,-2713 1903,-2761 1903,-2834 1936,-2867 2078.76,-2867 2110.76,-2899 2560,-2899 2593,-2866 2593,-2618 2577,-2602 2504,-2602 2474,-2572 2474,-2502 2394,-2422 2318,-2422 2255,-2359 2255,-2119 2474,-1900 3072,-1900 A5.1@3170,-1802
  Bottom Layer w15: R58.2@1869.98,-2226.46 v1(1869.98,-2262.46) R59.2@1896.05,-2262.46
A5_1: CN12.36 R57.2 | length 76
  Top Layer w30: CN12.36@2940,-1851 R57.2@3016,-1851
A6: A6.1 IC4.21 R60.1 R61.2 R62.2 | length 4540.5
  Top Layer w5: R60.1@2763,-1090 R60.1@2791,-1090 ; R60.1@2777,-1102 3070,-1102 A6.1@3170,-1002
  Top Layer w18: v1@1901.47,-2404.54 IC4.21@1901.47,-2335
  INT2 w5: v1(1901.92,-2404.54) 1901.92,-2249.92 1880,-2228 1338,-2228 1294,-2184 1294,-2079 1328,-2045 2171.54,-2045 2326,-1890.54 2326,-1779 2436,-1669 2436,-899 2494,-841 2727,-841 2766,-802 3051,-802 3098,-849 3098,-930 A6.1@3170,-1002
  Bottom Layer w15: R61.2@1901.92,-2440.54 v1(1901.92,-2404.54) R62.2@1928,-2404.54
A6_1: CN7.20 R60.2 | length 63
  Top Layer w30: CN7.20@2640,-1090 R60.2@2703,-1090
A7: A7.1 IC4.22 R63.1 R64.2 R65.2 | length 4523.5
  Top Layer w5: R63.1@2770,-1250 2770,-1249 2818,-1201 3071,-1201 A7.1@3170,-1102
  Top Layer w18: IC4.22@1932.97,-2335 v1(1932.97,-2262.46)
  INT2 w5: v1(1932.97,-2262.46) 1932.97,-2233.97 1911,-2212 1451,-2212 1425,-2186 1425,-2088 1452,-2061 2208,-2061 2351,-1918 2351,-1792 2460,-1683 2460,-1644 2501,-1603 2698,-1603 2740,-1561 2740,-1235 2693,-1188 2499,-1188 2458,-1147 2458,-973 2495,-936 2689,-936 2722.97,-902.03 2970.03,-902.03 A7.1@3170,-1102
  Bottom Layer w15: R64.2@1932.97,-2226.46 v1(1932.97,-2262.46) R65.2@1959.05,-2262.46
A7_1: CN10.2 R63.2 | length 63
  Top Layer w30: CN10.2@2640,-1250 R63.2@2703,-1250
A8: A8.1 IC4.23 R66.1 R67.2 R68.2 | length 4543.8
  Top Layer w5: R66.1@2771,-1550 2775.57,-1545.43 2775.57,-1525.43 2799,-1502 3070,-1502 A8.1@3170,-1402
  Top Layer w18: v1@1964.46,-2404.54 IC4.23@1964.46,-2335
  INT2 w5: v1(1964.91,-2404.54) 1964.91,-2236.91 1892,-2164 1609,-2164 1590,-2145 1590,-2098 1608,-2080 2231,-2080 2370,-1941 2370,-1818 2488,-1700 2745,-1700 2775,-1670 2775,-1202 2739,-1166 2509,-1166 2479,-1136 2479,-1074 2515,-1038 2725,-1038 2759,-1004 3011,-1004 3037,-1030 3037,-1269 A8.1@3170,-1402
  Bottom Layer w15: R67.2@1964.91,-2440.54 v1(1964.91,-2404.54) R68.2@1990.99,-2404.54
A8_1: CN10.8 R66.2 | length 63
  Top Layer w30: CN10.8@2640,-1550 R66.2@2703,-1550
A9: A9.1 IC4.24 R69.1 R70.2 R71.2 | length 4545.2
  Top Layer w5: R69.1@2770,-1750 2780.57,-1739.43 2780.57,-1725.43 2804,-1702 A9.1@3170,-1702
  Top Layer w18: IC4.24@1995.96,-2335 v1(1995.96,-2262.46)
  INT2 w5: v1(1995.96,-2262.46) 1995.96,-2169.04 2013,-2152 2062,-2152 2076,-2166 2076,-2360 2121,-2405 2121,-2559 2093,-2587 1810,-2587 1759,-2536 1664,-2536 1621,-2579 1621,-2651 1661,-2691 1880,-2691 1942,-2753 2387,-2753 2446,-2694 2446,-2506 2385,-2445 2297,-2445 2230,-2378 2230,-2114 2397,-1947 2397,-1881 2478,-1800 3010,-1800 3108,-1702 A9.1@3170,-1702
  Bottom Layer w15: R70.2@1995.96,-2226.46 v1(1995.96,-2262.46) R71.2@2022.04,-2262.46
A9_1: CN10.12 R69.2 | length 63
  Top Layer w30: CN10.12@2640,-1750 R69.2@2703,-1750
A10: A10.1 IC4.31 R117.1 R118.2 R119.2 | length 4544
  Top Layer w5: A10.1@225,-3000 266,-3000 365,-2901 567,-2901 R117.1@618,-2850
  Top Layer w18: IC4.31@1995.91,-1845 v1(1995.91,-1774.46)
  INT1 w5: A10.1@225,-3000 129,-2904 129,-2686 91,-2648 91,-2128 120,-2099 120,-1325 197,-1248 285,-1248 331,-1202 913,-1202 973,-1142 1265,-1142 1826,-1703 1924.46,-1703 v1(1995.91,-1774.46)
  Bottom Layer w15: R118.2@1995.91,-1738.46 v1(1995.91,-1774.46) R119.2@2021.99,-1774.46
A10_1: CN9.29 R117.2 | length 61
  Top Layer w30: R117.2@679,-2850 CN9.29@740,-2850
A11: A11.1 IC4.32 R114.1 R115.2 R116.2 | length 4542.8
  Top Layer w5: A11.1@225,-3100 326,-2999 573,-2999 R114.1@620,-2952
  Top Layer w18: v1(1964.46,-1915.54) IC4.32@1964.46,-1845
  INT1 w5: A11.1@225,-3100 268,-3057 268,-2971 244,-2947 201,-2947 153,-2899 153,-2660 115,-2622 115,-2144 146,-2113 146,-1496 189,-1453 271,-1453 321,-1503 603,-1503 720,-1386 902,-1386 981,-1307 1252,-1307 1653,-1708 1653,-1777 1764,-1888 1936.92,-1888 v1(1964.46,-1915.54)
  Bottom Layer w15: R115.2@1964.46,-1951.54 v1(1964.46,-1915.54) R116.2@1990.54,-1915.54
A11_1: CN9.30 R114.2 | length 202.2
  Top Layer w5: R114.2@680,-2952 738,-2952 CN9.30@840,-2850
A12: A12.1 IC4.33 R111.1 R112.2 R113.2 | length 4538.8
  Top Layer w5: A12.1@226.5,-1302.5 A12.1@225,-1301 325,-1201 R111.1@613,-1201
  Top Layer w18: IC4.33@1932.92,-1845 v1(1932.92,-1774.46)
  INT1 w5: A12.1@225,-1301 881,-1301 983,-1199 1280,-1199 1735,-1654 1735,-1715 1770,-1750 1770,-1821.87 1803.13,-1855 1965,-1855 2087,-1977 2158,-1977 2220,-1915 2413,-1915 2463,-1865 2463,-1482 2436,-1455 2146,-1455 2080,-1521 2080,-1786 2048,-1818 1976.46,-1818 v1(1932.92,-1774.46)
  Bottom Layer w15: R112.2@1932.92,-1738.46 v1(1932.92,-1774.46) R113.2@1959,-1774.46
A12_1: CN8.14 R111.2 | length 188.1
  Top Layer w5: R111.2@673,-1201 789,-1201 CN8.14@840,-1150
A13: A13.1 IC4.34 R108.1 R109.2 R110.2 | length 4538.5
  Top Layer w5: A13.1@225,-1401 327,-1299 R108.1@613,-1299
  Top Layer w18: v1(1901.47,-1915.54) IC4.34@1901.47,-1845
  INT1 w5: A13.1@225,-1401 644,-1401 707,-1338 896,-1338 1019,-1215 1268,-1215 1710,-1657 1710,-1802 1779,-1871 1956,-1871 2119,-2034 2119,-2106 2087,-2138 2016,-2138 1900,-2022 1451,-2022 1433,-2004 1433,-1847 1466,-1814 1653,-1814 1684,-1845 1684,-1927 1702,-1945 1872.02,-1945 v1(1901.47,-1915.54)
  Bottom Layer w15: R109.2@1901.47,-1951.54 v1(1901.47,-1915.54) R110.2@1927.55,-1915.54
A13_1: CN8.16 R108.2 | length 187.3
  Top Layer w5: R108.2@673,-1299 791,-1299 CN8.16@840,-1250
A14: A14.1 IC4.35 R105.1 R106.2 R107.2 | length 4540.4
  Top Layer w5: R105.1@2709,-3551 2709,-3584 2727,-3602 A14.1@3170,-3602
  Top Layer w18: IC4.35@1869.93,-1845 v1(1869.93,-1774.46)
  INT1 w5: v1(1869.93,-1774.46) 1899.39,-1745 1942,-1745 1959,-1762 1959,-1780 1979,-1800 2016,-1800 2058,-1758 2058,-1511 2137,-1432 2333,-1432 2367,-1398 2958,-1398 3004,-1444 3004,-1715 3042,-1753 3196,-1753 3266,-1823 3266,-2028 3266,-3506 A14.1@3170,-3602
  Bottom Layer w15: R106.2@1869.93,-1738.46 v1(1869.93,-1774.46) R107.2@1896.01,-1774.46
A14_1: CN12.69 R105.2 | length 108
  Top Layer w30: R105.2@2769,-3551 CN12.69@2823,-3551 ; R105.2@2786,-3551 CN12.69@2840,-3551
A15: A15.1 IC4.50 R78.1 R79.2 R80.2 | length 4544.5
  Top Layer w18: v1(1397.54,-1915.54) IC4.50@1397.54,-1845
  Top Layer w20: R78.1@3076,-3451 3121,-3451 A15.1@3170,-3402
  INT1 w5: v1(1397.54,-1915.54) 1414,-1932.01 1414,-2014 1438,-2038 1893,-2038 2044,-2189 2044,-2456 2094,-2506 2143,-2506 2186,-2463 2186,-1983 2225,-1944 2425,-1944 2453,-1972 2453,-2062 2488,-2097 2999,-2097 3043,-2053 3197,-2053 3246,-2102 3246,-3326 A15.1@3170,-3402
  Bottom Layer w15: R80.2@1371.46,-1915.54 v1(1397.54,-1915.54) R79.2@1397.54,-1951.54
A15_1: CN12.68 R78.2 | length 76
  Top Layer w30: CN12.68@2940,-3451 R78.2@3016,-3451
A16: A16.1 IC4.51 R75.1 R76.2 R77.2 | length 4531.7
  Top Layer w5: R75.1@2763,-2301 2986,-2301 3040,-2355 3123,-2355 A16.1@3170,-2402
  Top Layer w18: IC4.51@1366.04,-1845 v1(1365.99,-1774.46)
  INT1 w5: v1(1365.99,-1774.46) 1335.53,-1744 1287,-1744 1272,-1759 1272,-1810 1311,-1849 1311,-2041 1380,-2110 1742,-2110 1839,-2207 1839,-2306 1863,-2330 1863,-2697 1685,-2875 1685,-3040 1755,-3110 1860.1,-3110 1923,-3047.1 1923,-2849 2026,-2746 2348,-2746 2482,-2612 2482,-2437 2517,-2402 A16.1@3170,-2402
  Bottom Layer w15: R77.2@1339.91,-1774.46 v1(1365.99,-1774.46) R76.2@1365.99,-1738.46
A16_1: CN10.23 R75.2 | length 181.2
  Top Layer w5: CN10.23@2540,-2350 2584,-2306 R75.2@2703,-2306
A17: A17.1 IC4.52 R72.1 R73.2 R74.2 | length 4560.9
  Top Layer w5: R72.1@2765,-2198 3166,-2198 A17.1@3169,-2201
  Top Layer w18: v1(1334.54,-1915.54) IC4.52@1334.54,-1845
  INT1 w5: v1(1334.54,-1915.54) 1334.54,-2031.54 1385,-2082 1763,-2082 1904,-2223 1904,-2324 1929,-2349 1929,-2417 1884,-2462 1884,-2702 1861,-2725 1861,-2765.2 1886.8,-2791 1950,-2791 2020,-2721 2339,-2721 2457,-2603 2457,-2418 2433,-2394 2273,-2394 2233,-2354 2233,-2024 2260,-1997 2371,-1997 2407,-2033 2407,-2222 2488,-2303 3069,-2303 A17.1@3170,-2202
  Bottom Layer w15: R74.2@1308.46,-1915.54 v1(1334.54,-1915.54) R73.2@1334.54,-1951.54
A17_1: CN10.21 R72.2 | length 186.5
  Top Layer w5: CN10.21@2540,-2250 2592,-2198 R72.2@2705,-2198
A18: A18.1 IC4.53 R1.1 R2.2 R3.2 | length 4546.4
  Top Layer w5: R1.1@2765,-2099 3167,-2099 A18.1@3170,-2102
  Top Layer w18: IC4.53@1303,-1845 v1(1303,-1774.46)
  INT1 w5: v1(1303,-1774.46) 1365,-1836.46 1365,-1944 1393,-1972 1393,-2034 1419,-2060 1817,-2060 1927,-2170 1927,-2212 1955,-2240 1955,-2292 1989,-2326 1989,-2418.85 1959,-2448.85 1959,-2491 1902,-2548 1902,-2679 1925,-2702 2327,-2702 2432,-2597 2432,-2449 2400,-2417 2267,-2417 2211,-2361 2211,-1998 2240,-1969 2406,-1969 2430,-1993 2430,-2151 2477,-2198 3074,-2198 A18.1@3170,-2102
  Bottom Layer w15: R3.2@1276.92,-1774.46 v1(1303,-1774.46) R2.2@1303,-1738.46
A18_1: CN10.19 R1.2 | length 186.1
  Top Layer w5: CN10.19@2540,-2150 2591,-2099 R1.2@2705,-2099
A19: A19.1 IC4.2 R4.1 R5.2 R6.2 | length 4526.5
  Top Layer w5: A19.1@225,-2300 R4.1@605,-2300
  Top Layer w18: IC4.2@1303.05,-2335 v1(1303.05,-2262.46)
  INT1 w5: A19.1@225,-2300 162,-2363 162,-2524 187,-2549 262,-2549 298,-2585 298,-2638 358,-2698 465,-2698 490,-2723 490,-2884 504,-2898 563,-2898 590,-2925 590,-2984 685,-3079 685,-3231 801,-3347 1052,-3347 1066,-3333 1066,-3284 1049,-3267 945,-3267 917,-3239 917,-2924 954,-2887 1048,-2887 1076,-2859 1076,-2809 1047,-2780 950,-2780 920,-2750 920,-2210 973,-2157 973,-2023 1023,-1973 1175,-1973 1210,-2008 1210,-2080 1303.05,-2173.05 v1(1303.05,-2262.46)
  Bottom Layer w15: R6.2@1276.97,-2262.46 v1(1303.05,-2262.46) R5.2@1303.05,-2226.46
A19_1: CN9.22 R4.2 | length 283.4
  Top Layer w5: R4.2@665,-2300 769,-2300 791,-2322 791,-2401 CN9.22@840,-2450
A20: A20.1 IC4.1 R7.1 R8.2 R9.2 | length 4531.4
  Top Layer w5: A20.1@225,-2100 R7.1@606,-2100
  Top Layer w18: v1@1271.55,-2404.54 IC4.1@1271.55,-2335
  INT1 w5: A20.1@225,-2100 142,-2183 142,-2592 201,-2651 246,-2651 367,-2772 367,-3041 425,-3099 571,-3099 647,-3175 647,-3257 789,-3399 1066,-3399 1106,-3359 1106,-3251 1084,-3229 975,-3229 955,-3209 955,-3119 982,-3092 1053,-3092 1155,-2990 1205,-2990 1235,-2960 1235,-2794 1182,-2741 979,-2741 953,-2715 953,-2321 982,-2292 1056,-2292 1168.54,-2404.54 v1(1272,-2404.54)
  Bottom Layer w10: v1@1271.54,-2405 v1(1272,-2404.54) ; R8.2@1272,-2441.55 R8.2@1272.45,-2442
  Bottom Layer w15: R9.2@1240.45,-2405 v1@1271.54,-2405 ; R8.2@1272,-2441.55 v1(1272,-2404.54)
A20_1: CN9.16 R7.2 | length 194.3
  Top Layer w5: R7.2@666,-2100.89 790.88,-2100.89 CN9.16@840,-2150
A21: A21.1 IC4.54 R136.1 R137.2 R138.2 | length 4539.4
  Top Layer w5: A21.1@225,-2200 R136.1@606,-2200
  Top Layer w18: v1(1271.55,-1915.54) IC4.54@1271.55,-1845
  INT1 w5: A21.1@225,-2200 279,-2254 279,-2441 339,-2501 565,-2501 611,-2547 611,-2860 639,-2888 639,-2965 724,-3050 724,-3206 749,-3231 836,-3231 863,-3204 863,-2975 799,-2911 799,-2339 753,-2293 396,-2293 386,-2283 386,-2019 406,-1999 892,-1999 975.46,-1915.54 v1(1271.55,-1915.54)
  Bottom Layer w15: R138.2@1245.47,-1915.54 v1(1271.55,-1915.54) R137.2@1271.55,-1951.54
A21_1: CN9.18 R136.2 | length 194.3
  Top Layer w5: R136.2@666,-2200.89 790.88,-2200.89 CN9.18@840,-2250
